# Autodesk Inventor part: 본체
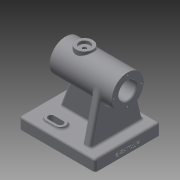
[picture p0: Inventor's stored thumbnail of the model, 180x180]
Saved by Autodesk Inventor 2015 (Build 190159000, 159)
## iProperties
Created: 2022-06
Part Number: 본체
Material: 일반
Document SubType Name: Modeling
Designer: 1048888
Density: 1 g/cm^3
Appearance: 기본값
Mass: 234.742 g
Surface Area: 513.531 cm^2
Volume: 234.742 cm^3
Author: 1048888
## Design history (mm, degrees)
sketch "스케치1"
  geometry: L1 (-50, -43)-(50, -43); L2 (50, -43)-(50, 43); L3 (50, 43)-(-50, 43); L4 (-50, 43)-(-50, -43); L5 (-50, -43)-(50, 43); L6 (50, -43)-(-50, 43); 1 further point
  constraints: 12 end point, 2 midpoint, 2 parallel, 1 horizontal, 1 perpendicular
  dimensions: "d2" = 100 distance of L2.end L3.end; "d3" = 86 distance of L1.end L2.end
extrude "돌출1" new body sketch "스케치1" distance "d4" = 15; taper "d5" = 0 deg
fillet "모깎기1" dims "d6" = 3
fillet "모깎기2" dims "d7" = 3
sketch "스케치2"
  geometry: L1 (-35, 5)-(35, 5); L2 (35, 5)-(35, -5); L3 (35, -5)-(-35, -5); L4 (-35, -5)-(-35, 5); L5 (-35, 5)-(35, -5); L6 (35, 5)-(-35, -5); L7 (50, -40)-(50, 40) reference; L8 (47, 43)-(-47, 43) reference; 4 further points
  constraints: 12 end point, 3 midpoint, 2 parallel, 1 horizontal, 1 horizontal alignment, 1 perpendicular
  dimensions: "d10" = 10 distance of L3.end L1.start; "d26" = 15 distance between parallel lines of L7 L2
extrude "돌출2" join sketch "스케치2" distance "d12" = 57; taper "d13" = 0 deg
sketch "스케치3"
  geometry: L1 (-24, 27)-(-12, 27); L2 (-24, 20)-(-12, 20); L3 (-12, 34)-(-24, 34); L4 (-50, 40)-(-50, -40) reference; L5 (47, 43)-(-47, 43) reference; A1 r 7 centre (-24, 27) between (-24, 34) and (-24, 20); A2 r 7 centre (-12, 27) between (-12, 20) and (-12, 34); 2 further points
  constraints: 8 end point, 4 point on circle, 4 tangent, 2 centre point, 1 horizontal, 1 midpoint, 1 parallel
  dimensions: "d16" = 26 distance from line of L4 L1.start; "d17" = 12 distance of L1.start L1.end; "d18" = 16 distance between parallel lines of L1 L5; "d19" = 7 radius of A1
extrude "돌출3" join sketch "스케치3" distance "d20" = 3; taper "d21" = 0 deg
sketch "스케치4"
  geometry: L1 (-24, 20)-(-12, 20) reference; L2 (-12, 34)-(-24, 34) reference; L3 (-24, 23)-(-12, 23); L4 (-12, 31)-(-24, 31); A1 r 7 centre (-12, 27) between (-12, 20) and (-12, 34) reference; A2 r 7 centre (-24, 27) between (-24, 34) and (-24, 20) reference; A3 r 4 centre (-12, 27) between (-12, 23) and (-12, 31); A4 r 4 centre (-24, 27) between (-24, 31) and (-24, 23); 1 further point
  constraints: 4 end point, 4 point on circle, 2 centre point, 3 other
  dimensions: "d22" = 3 radial gap between concentric circles of A2 A4
extrude "돌출4" cut sketch "스케치4" stored distance "d23" = 3; taper "d24" = 0 deg
fillet "모깎기5" dims "d25" = 3
sketch "스케치7"
  geometry: L1 (0, 80)-(0, 0) reference; L2 (0, 0)-(-12, 0) reference; L3 (-12, 0)-(-12, 80) reference; L4 (0, 80)-(-12, 80) reference; L5 (-72, 35)-(-72, 45) reference; C1 r 21 at (-72, 40); 2 further points
  constraints: 1 centre point, 1 coincident, 1 midpoint
  dimensions: "d28" = 42 diameter of C1
extrude "돌출5" join sketch "스케치7" distance "d29" = 82; taper "d30" = 0 deg
feature "면 기울기1" dims angle "d31" = 20 deg
node "작업 평면1"
sketch "스케치8"
  geometry: L1 (-40, 15)-(-5, 15) reference; L2 (-5, 15)-(5, 15) reference; L3 (5, 51.604)-(5, 15) reference; L4 (-5, 15)-(-5, 51.604) reference; L5 (-43, 0)-(-43, 12) reference; L6 (43, 0)-(-43, 0) reference; L7 (43, 12)-(43, 0) reference; L8 (5, 15)-(40, 15) reference; L9 (-35, 15)-(-20.441, 76.814); L10 (-20.441, 76.814)-(20.441, 76.814); L11 (20.441, 76.814)-(35, 15); L12 (35, 15)-(-35, 15); A1 r 21 centre (0, 72) between (5, 51.604) and (-5, 51.604) reference; A2 r 3 centre (-40, 12) between (-40, 15) and (-43, 12) reference; A3 r 3 centre (40, 12) between (43, 12) and (40, 15) reference; A4 r 21 centre (0, 72) between (-5, 51.604) and (5, 51.604) reference; 2 further points
  constraints: 8 end point, 2 point on circle, 2 tangent, 1 collinear, 1 midpoint
  dimensions: "d33" = 8 distance from line of L5 L9.start; "d34" = 8 distance from line of L11.end L7
extrude "돌출6" join sketch "스케치8" distance "d36" = 10; taper "d37" = 0 deg
fillet "모깎기6" dims "d38" = 3
fillet "모깎기7" dims "d39" = 3
fillet "모깎기8" dims "d40" = 3
sketch "스케치9"
  geometry: C1 r 21 at (0, 0) reference; 1 further point
hole "구멍1" sketch "스케치9" at (0, 0) diameter "d41" = 23; stored, may be unused: countersink angle "d45" = 90 deg, drill point angle "d47" = 118 deg; dims "d42" = 6, "d43" = 29, "d44" = 62, "d46" = 8
node "작업 평면2"
sketch "스케치10"
  geometry: L1 (-32, 21)-(-32, -21) reference; C1 r 11 at (-7, 0); 1 further point
  constraints: 1 centre point, 1 horizontal alignment
  dimensions: "d49" = 22 diameter of C1; "d50" = 25 distance from line of L1 C1.centre
extrude "돌출7" join sketch "스케치10" stored distance "d51" = 10; taper "d52" = 0 deg
sketch "스케치11"
  geometry: C1 r 11 at (0, 0) reference; C2 r 7 at (0, 0); 1 further point
  constraints: 1 centre point, 1 coincident
  dimensions: "d53" = 14 diameter of C2
extrude "돌출8" cut sketch "스케치11" distance "d54" = 4; taper "d55" = 0 deg
sketch "스케치12"
  geometry: 2 further points
  constraints: 1 horizontal alignment
hole "구멍2" sketch "스케치12" at (0, 0) diameter "d56" = 4.917; stored, may be unused: countersink angle "d60" = 90 deg, drill point angle "d62" = 118 deg; dims "d57" = 12, "d58" = 29, "d59" = 62, "d61" = 24
sketch "스케치13"
  geometry: C1 r 14.5 at (0, 0) reference; 2 further points
  constraints: 1 horizontal alignment
  dimensions: "d63" = 18 distance of C1.centre point (18, 0)
hole "구멍3" sketch "스케치13" at (18, 0) diameter "d64" = 2.459; stored, may be unused: countersink angle "d68" = 90 deg, drill point angle "d70" = 118 deg; dims "d65" = 8, "d66" = 29, "d67" = 62, "d69" = 10
sketch "스케치14"
  geometry: C1 r 11.5 at (0, 0) reference; 2 further points
  constraints: 1 horizontal alignment
  dimensions: "d74" = 18 distance of C1.centre point (-18, 0)
hole "구멍4" sketch "스케치14" at (-18, 0) diameter "d75" = 2.459; stored, may be unused: countersink angle "d79" = 90 deg, drill point angle "d81" = 118 deg; dims "d76" = 8, "d77" = 29, "d78" = 62, "d80" = 10
sketch "스케치15"
  geometry: L1 (0, 0)-(0, 80) reference; 3 further points
  constraints: 1 horizontal alignment, 1 midpoint, 1 other
  dimensions: "d85" = 6 distance from line of L1 point (-6, 40)
feature "엠보싱1" sketch "스케치15" dims "d2" = 100, "d3" = 86, "d10" = 10, "d26" = 15, "d86" = 0.5, "d87" = 0
chamfer "모따기1" distance "d88" = 1; stored, may be unused: second distance "d89" = 2, angle "d90" = 45 deg
fillet "모깎기9" dims "d91" = 1
node "솔리드1"
mirror "대칭1"
pattern_circular "원형 패턴1" dims angle "d72" = 360 deg
pattern_circular "원형 패턴2" dims angle "d83" = 360 deg
node "절단 모서리 투영2"
node "절단 모서리 투영3"
other parameters: "d32" = 35, "d48" = 96
